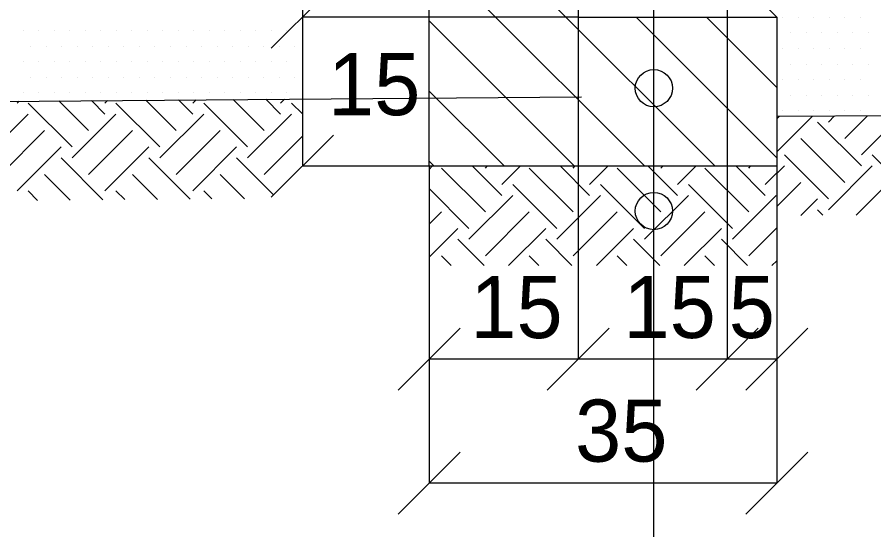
# Model space of a CAD drawing. Extents: x -219625893 to 7498339, y 5791790 to 5792761.
# Drawn here: x 7495350.16 to 7495367.41, y 5791855.88 to 5791866.2 of the extents above; entities that cross this region are included whole.
import ezdxf

# ---------------------------------------------------------------- set-up
doc = ezdxf.new("R2010")
doc.units = 0
for name, color, linetype in [('D_kons_wyp_grunt', 7, 'Continuous'), ('D_kons_wyp_pospolka', 7, 'Continuous'), ('D_robocze_1', 7, 'Continuous'), ('D_wymiary_500', 7, 'Continuous'), ('Level 10', 7, 'Continuous'), ('Level 8', 7, 'Continuous'), ('wymiary', 7, 'Continuous')]:
    doc.layers.add(name, color=color, linetype=linetype)

msp = doc.modelspace()

# ---------------------------------------------------------------- linework, layer by layer
at = {"layer": 'D_kons_wyp_grunt'}
for p, q in [((7495355.136, 5791863.919), (7495354.511, 5791864.543)), ((7495355.467, 5791864.25), (7495355.169, 5791864.549)), ((7495355.467, 5791864.471), (7495355.548, 5791864.552)), ((7495350.164, 5791864.471), (7495350.202, 5791864.509)), ((7495351.269, 5791863.587), (7495350.385, 5791864.471)), ((7495351.6, 5791863.919), (7495351.004, 5791864.515)), ((7495351.932, 5791864.25), (7495351.662, 5791864.521)), ((7495351.932, 5791864.471), (7495351.984, 5791864.523)), ((7495353.037, 5791863.587), (7495352.153, 5791864.471)), ((7495353.368, 5791863.919), (7495352.758, 5791864.529)), ((7495353.7, 5791864.25), (7495353.415, 5791864.535)), ((7495353.7, 5791864.471), (7495353.766, 5791864.538)), ((7495354.804, 5791863.587), (7495353.921, 5791864.471)), ((7495355.906, 5791864.254), (7495355.688, 5791864.471)), ((7495349.501, 5791863.367), (7495350.385, 5791864.25)), ((7495351.269, 5791863.367), (7495352.153, 5791864.25)), ((7495353.037, 5791863.367), (7495353.921, 5791864.25)), ((7495354.804, 5791863.367), (7495355.688, 5791864.25)), ((7495365.458, 5791863.492), (7495366.177, 5791864.21)), ((7495365.458, 5791864.155), (7495365.51, 5791864.207)), ((7495366.497, 5791864.089), (7495366.621, 5791864.213)), ((7495366.828, 5791863.757), (7495367.287, 5791864.216)), ((7495367.16, 5791863.426), (7495367.953, 5791864.219)), ((7495367.16, 5791863.205), (7495366.276, 5791864.089)), ((7495349.833, 5791863.035), (7495350.716, 5791863.919)), ((7495351.6, 5791863.035), (7495352.484, 5791863.919)), ((7495353.368, 5791863.035), (7495354.252, 5791863.919)), ((7495355.136, 5791863.035), (7495355.906, 5791863.805)), ((7495366.828, 5791862.873), (7495365.944, 5791863.757)), ((7495350.164, 5791862.704), (7495351.048, 5791863.587)), ((7495351.932, 5791862.704), (7495352.816, 5791863.587)), ((7495353.7, 5791862.704), (7495354.583, 5791863.587)), ((7495351.892, 5791862.522), (7495351.048, 5791863.367)), ((7495353.646, 5791862.536), (7495352.816, 5791863.367)), ((7495355.328, 5791862.622), (7495354.583, 5791863.367)), ((7495366.497, 5791862.542), (7495365.613, 5791863.426)), ((7495368.265, 5791862.542), (7495367.381, 5791863.426)), ((7495358.458, 5791863.135), (7495358.523, 5791863.199)), ((7495359.591, 5791862.279), (7495358.707, 5791863.163)), ((7495359.922, 5791862.61), (7495359.333, 5791863.199)), ((7495359.591, 5791863.163), (7495359.627, 5791863.199)), ((7495359.922, 5791862.831), (7495360.29, 5791863.199)), ((7495361.359, 5791862.279), (7495360.475, 5791863.163)), ((7495361.69, 5791862.61), (7495361.101, 5791863.199)), ((7495361.359, 5791863.163), (7495361.395, 5791863.199)), ((7495361.69, 5791862.831), (7495362.058, 5791863.199)), ((7495363.126, 5791862.279), (7495362.242, 5791863.163)), ((7495363.458, 5791862.61), (7495362.869, 5791863.199)), ((7495363.126, 5791863.163), (7495363.163, 5791863.199)), ((7495363.458, 5791862.831), (7495363.826, 5791863.199)), ((7495364.894, 5791862.279), (7495364.01, 5791863.163)), ((7495365.226, 5791862.61), (7495364.637, 5791863.199)), ((7495364.894, 5791863.163), (7495364.931, 5791863.199)), ((7495365.458, 5791863.05), (7495365.613, 5791863.205)), ((7495366.497, 5791862.321), (7495367.381, 5791863.205)), ((7495351.234, 5791862.517), (7495350.716, 5791863.035)), ((7495352.988, 5791862.531), (7495352.484, 5791863.035)), ((7495354.742, 5791862.545), (7495354.252, 5791863.035)), ((7495365.226, 5791862.831), (7495365.458, 5791863.064)), ((7495361.027, 5791861.948), (7495360.143, 5791862.831)), ((7495362.795, 5791861.948), (7495361.911, 5791862.831)), ((7495364.563, 5791861.948), (7495363.679, 5791862.831)), ((7495365.458, 5791862.387), (7495365.944, 5791862.873)), ((7495367.054, 5791862.215), (7495367.712, 5791862.873)), ((7495350.577, 5791862.512), (7495350.385, 5791862.704)), ((7495352.33, 5791862.526), (7495352.153, 5791862.704)), ((7495354.084, 5791862.54), (7495353.921, 5791862.704)), ((7495359.259, 5791861.948), (7495358.458, 5791862.749)), ((7495359.259, 5791861.727), (7495360.143, 5791862.61)), ((7495361.027, 5791861.727), (7495361.911, 5791862.61)), ((7495362.795, 5791861.727), (7495363.679, 5791862.61)), ((7495364.563, 5791861.727), (7495365.447, 5791862.61)), ((7495365.943, 5791862.209), (7495366.276, 5791862.542)), ((7495366.385, 5791862.211), (7495366.276, 5791862.321)), ((7495358.458, 5791862.03), (7495358.707, 5791862.279)), ((7495359.591, 5791861.395), (7495360.475, 5791862.279)), ((7495361.359, 5791861.395), (7495362.242, 5791862.279)), ((7495363.126, 5791861.395), (7495364.01, 5791862.279)), ((7495364.894, 5791861.395), (7495365.458, 5791861.959)), ((7495358.458, 5791861.367), (7495359.038, 5791861.948)), ((7495360.058, 5791861.199), (7495360.806, 5791861.948)), ((7495361.826, 5791861.199), (7495362.574, 5791861.948)), ((7495363.594, 5791861.199), (7495364.342, 5791861.948)), ((7495359.566, 5791861.199), (7495359.038, 5791861.727)), ((7495361.333, 5791861.199), (7495360.806, 5791861.727)), ((7495363.101, 5791861.199), (7495362.574, 5791861.727)), ((7495364.869, 5791861.199), (7495364.342, 5791861.727)), ((7495358.903, 5791861.199), (7495358.707, 5791861.395)), ((7495360.67, 5791861.199), (7495360.475, 5791861.395)), ((7495362.438, 5791861.199), (7495362.242, 5791861.395)), ((7495364.206, 5791861.199), (7495364.01, 5791861.395)), ((7495365.361, 5791861.199), (7495365.458, 5791861.296))]:
    msp.add_line(p, q, dxfattribs=at)
at = {"layer": 'D_kons_wyp_pospolka'}
for p, q in [((7495365.58, 5791866.195), (7495365.58, 5791866.195)), ((7495365.892, 5791866.195), (7495365.892, 5791866.195)), ((7495366.205, 5791866.195), (7495366.205, 5791866.195)), ((7495366.517, 5791866.195), (7495366.517, 5791866.195)), ((7495366.83, 5791866.195), (7495366.83, 5791866.195)), ((7495367.142, 5791866.195), (7495367.142, 5791866.195)), ((7495350.283, 5791865.932), (7495350.283, 5791865.932)), ((7495350.596, 5791865.932), (7495350.596, 5791865.932)), ((7495350.908, 5791865.932), (7495350.908, 5791865.932)), ((7495351.221, 5791865.932), (7495351.221, 5791865.932)), ((7495351.533, 5791865.932), (7495351.533, 5791865.932)), ((7495351.846, 5791865.932), (7495351.846, 5791865.932)), ((7495352.158, 5791865.932), (7495352.158, 5791865.932)), ((7495352.471, 5791865.932), (7495352.471, 5791865.932)), ((7495352.783, 5791865.932), (7495352.783, 5791865.932)), ((7495353.096, 5791865.932), (7495353.096, 5791865.932)), ((7495353.408, 5791865.932), (7495353.408, 5791865.932)), ((7495353.721, 5791865.932), (7495353.721, 5791865.932)), ((7495354.033, 5791865.932), (7495354.033, 5791865.932)), ((7495354.346, 5791865.932), (7495354.346, 5791865.932)), ((7495354.658, 5791865.932), (7495354.658, 5791865.932)), ((7495354.971, 5791865.932), (7495354.971, 5791865.932)), ((7495355.283, 5791865.932), (7495355.283, 5791865.932)), ((7495355.596, 5791865.932), (7495355.596, 5791865.932)), ((7495365.736, 5791865.883), (7495365.736, 5791865.883)), ((7495366.048, 5791865.883), (7495366.048, 5791865.883)), ((7495366.361, 5791865.883), (7495366.361, 5791865.883)), ((7495366.673, 5791865.883), (7495366.673, 5791865.883)), ((7495366.986, 5791865.883), (7495366.986, 5791865.883)), ((7495367.298, 5791865.883), (7495367.298, 5791865.883)), ((7495350.439, 5791865.619), (7495350.439, 5791865.619)), ((7495350.752, 5791865.619), (7495350.752, 5791865.619)), ((7495351.064, 5791865.619), (7495351.064, 5791865.619)), ((7495351.377, 5791865.619), (7495351.377, 5791865.619)), ((7495351.689, 5791865.619), (7495351.689, 5791865.619)), ((7495352.002, 5791865.619), (7495352.002, 5791865.619)), ((7495352.314, 5791865.619), (7495352.314, 5791865.619)), ((7495352.627, 5791865.619), (7495352.627, 5791865.619)), ((7495352.939, 5791865.619), (7495352.939, 5791865.619)), ((7495353.252, 5791865.619), (7495353.252, 5791865.619)), ((7495353.564, 5791865.619), (7495353.564, 5791865.619)), ((7495353.877, 5791865.619), (7495353.877, 5791865.619)), ((7495354.189, 5791865.619), (7495354.189, 5791865.619)), ((7495354.502, 5791865.619), (7495354.502, 5791865.619)), ((7495354.814, 5791865.619), (7495354.814, 5791865.619)), ((7495355.127, 5791865.619), (7495355.127, 5791865.619)), ((7495355.439, 5791865.619), (7495355.439, 5791865.619)), ((7495355.752, 5791865.619), (7495355.752, 5791865.619)), ((7495365.58, 5791865.57), (7495365.58, 5791865.57)), ((7495365.892, 5791865.57), (7495365.892, 5791865.57)), ((7495366.205, 5791865.57), (7495366.205, 5791865.57)), ((7495366.517, 5791865.57), (7495366.517, 5791865.57)), ((7495366.83, 5791865.57), (7495366.83, 5791865.57)), ((7495367.142, 5791865.57), (7495367.142, 5791865.57)), ((7495350.283, 5791865.307), (7495350.283, 5791865.307)), ((7495350.596, 5791865.307), (7495350.596, 5791865.307)), ((7495350.908, 5791865.307), (7495350.908, 5791865.307)), ((7495351.221, 5791865.307), (7495351.221, 5791865.307)), ((7495351.533, 5791865.307), (7495351.533, 5791865.307)), ((7495351.846, 5791865.307), (7495351.846, 5791865.307)), ((7495352.158, 5791865.307), (7495352.158, 5791865.307)), ((7495352.471, 5791865.307), (7495352.471, 5791865.307)), ((7495352.783, 5791865.307), (7495352.783, 5791865.307)), ((7495353.096, 5791865.307), (7495353.096, 5791865.307)), ((7495353.408, 5791865.307), (7495353.408, 5791865.307)), ((7495353.721, 5791865.307), (7495353.721, 5791865.307)), ((7495354.033, 5791865.307), (7495354.033, 5791865.307)), ((7495354.346, 5791865.307), (7495354.346, 5791865.307)), ((7495354.658, 5791865.307), (7495354.658, 5791865.307)), ((7495354.971, 5791865.307), (7495354.971, 5791865.307)), ((7495355.283, 5791865.307), (7495355.283, 5791865.307)), ((7495355.596, 5791865.307), (7495355.596, 5791865.307)), ((7495365.736, 5791865.258), (7495365.736, 5791865.258)), ((7495366.048, 5791865.258), (7495366.048, 5791865.258)), ((7495366.361, 5791865.258), (7495366.361, 5791865.258)), ((7495366.673, 5791865.258), (7495366.673, 5791865.258)), ((7495366.986, 5791865.258), (7495366.986, 5791865.258)), ((7495367.298, 5791865.258), (7495367.298, 5791865.258)), ((7495350.439, 5791864.994), (7495350.439, 5791864.994)), ((7495350.752, 5791864.994), (7495350.752, 5791864.994)), ((7495351.064, 5791864.994), (7495351.064, 5791864.994)), ((7495351.377, 5791864.994), (7495351.377, 5791864.994)), ((7495351.689, 5791864.994), (7495351.689, 5791864.994)), ((7495352.002, 5791864.994), (7495352.002, 5791864.994)), ((7495352.314, 5791864.994), (7495352.314, 5791864.994)), ((7495352.627, 5791864.994), (7495352.627, 5791864.994)), ((7495352.939, 5791864.994), (7495352.939, 5791864.994)), ((7495353.252, 5791864.994), (7495353.252, 5791864.994)), ((7495353.564, 5791864.994), (7495353.564, 5791864.994)), ((7495353.877, 5791864.994), (7495353.877, 5791864.994)), ((7495354.189, 5791864.994), (7495354.189, 5791864.994)), ((7495354.502, 5791864.994), (7495354.502, 5791864.994)), ((7495354.814, 5791864.994), (7495354.814, 5791864.994)), ((7495355.127, 5791864.994), (7495355.127, 5791864.994)), ((7495355.439, 5791864.994), (7495355.439, 5791864.994)), ((7495355.752, 5791864.994), (7495355.752, 5791864.994)), ((7495365.58, 5791864.945), (7495365.58, 5791864.945)), ((7495365.892, 5791864.945), (7495365.892, 5791864.945)), ((7495366.205, 5791864.945), (7495366.205, 5791864.945)), ((7495366.517, 5791864.945), (7495366.517, 5791864.945)), ((7495366.83, 5791864.945), (7495366.83, 5791864.945)), ((7495367.142, 5791864.945), (7495367.142, 5791864.945)), ((7495350.283, 5791864.682), (7495350.283, 5791864.682)), ((7495350.596, 5791864.682), (7495350.596, 5791864.682)), ((7495350.908, 5791864.682), (7495350.908, 5791864.682)), ((7495351.221, 5791864.682), (7495351.221, 5791864.682)), ((7495351.533, 5791864.682), (7495351.533, 5791864.682)), ((7495351.846, 5791864.682), (7495351.846, 5791864.682)), ((7495352.158, 5791864.682), (7495352.158, 5791864.682)), ((7495352.471, 5791864.682), (7495352.471, 5791864.682)), ((7495352.783, 5791864.682), (7495352.783, 5791864.682)), ((7495353.096, 5791864.682), (7495353.096, 5791864.682)), ((7495353.408, 5791864.682), (7495353.408, 5791864.682)), ((7495353.721, 5791864.682), (7495353.721, 5791864.682)), ((7495354.033, 5791864.682), (7495354.033, 5791864.682)), ((7495354.346, 5791864.682), (7495354.346, 5791864.682)), ((7495354.658, 5791864.682), (7495354.658, 5791864.682)), ((7495354.971, 5791864.682), (7495354.971, 5791864.682)), ((7495355.283, 5791864.682), (7495355.283, 5791864.682)), ((7495355.596, 5791864.682), (7495355.596, 5791864.682)), ((7495365.736, 5791864.633), (7495365.736, 5791864.633)), ((7495366.048, 5791864.633), (7495366.048, 5791864.633)), ((7495366.361, 5791864.633), (7495366.361, 5791864.633)), ((7495366.673, 5791864.633), (7495366.673, 5791864.633)), ((7495366.986, 5791864.633), (7495366.986, 5791864.633)), ((7495367.298, 5791864.633), (7495367.298, 5791864.633)), ((7495365.58, 5791864.32), (7495365.58, 5791864.32)), ((7495365.892, 5791864.32), (7495365.892, 5791864.32)), ((7495366.205, 5791864.32), (7495366.205, 5791864.32)), ((7495366.517, 5791864.32), (7495366.517, 5791864.32)), ((7495366.83, 5791864.32), (7495366.83, 5791864.32)), ((7495367.142, 5791864.32), (7495367.142, 5791864.32))]:
    msp.add_line(p, q, dxfattribs=at)
at = {"layer": 'D_robocze_1'}
for p, q in [((7495364.216, 5791863.199), (7495358.458, 5791868.957)), ((7495362.801, 5791863.199), (7495358.458, 5791867.543)), ((7495361.387, 5791863.199), (7495358.458, 5791866.128)), ((7495365.458, 5791863.371), (7495362.63, 5791866.199)), ((7495365.458, 5791864.785), (7495364.044, 5791866.199)), ((7495359.973, 5791863.199), (7495358.458, 5791864.714)), ((7495358.559, 5791863.199), (7495358.458, 5791863.3))]:
    msp.add_line(p, q, dxfattribs=at)
at = {"layer": 'D_wymiary_500'}
for p, q in [((7495355.906, 5791869.199), (7495355.906, 5791863.199)), ((7495364.458, 5791867.199), (7495364.458, 5791859.316)), ((7495361.458, 5791866.199), (7495355.906, 5791866.199)), ((7495361.458, 5791866.199), (7495361.458, 5791859.316)), ((7495365.458, 5791864.207), (7495414.458, 5791864.452)), ((7495358.458, 5791863.199), (7495355.906, 5791863.199)), ((7495358.458, 5791863.199), (7495358.458, 5791856.816)), ((7495365.458, 5791863.199), (7495365.458, 5791856.816)), ((7495365.458, 5791859.316), (7495358.458, 5791859.316)), ((7495365.458, 5791856.816), (7495358.458, 5791856.816))]:
    msp.add_line(p, q, dxfattribs=at)
at = {"layer": 'Level 10'}
for p, q in [((7495359.094, 5791863.199), (7495359.094, 5791863.199)), ((7495363.337, 5791863.199), (7495363.337, 5791863.199))]:
    msp.add_line(p, q, dxfattribs=at)
at = {"layer": 'Level 8'}
for p, q in [((7495358.458, 5791863.199), (7495358.458, 5791869.199)), ((7495364.458, 5791867.199), (7495365.458, 5791866.199)), ((7495365.458, 5791866.199), (7495365.458, 5791863.199)), ((7495365.458, 5791863.199), (7495358.458, 5791863.199))]:
    msp.add_line(p, q, dxfattribs=at)
msp.add_lwpolyline([(7495361.458, 5791867.199), (7495361.458, 5791866.199), (7495365.458, 5791866.199)], dxfattribs=at)
at = {"layer": 'wymiary'}
for p, q in [((7495362.983, 5791843.439), (7495362.983, 5791869.945)), ((7495355.28, 5791865.575), (7495356.531, 5791866.824)), ((7495298.471, 5791864.094), (7495361.527, 5791864.6)), ((7495355.28, 5791862.575), (7495356.531, 5791863.824)), ((7495357.833, 5791858.691), (7495359.084, 5791859.94)), ((7495360.833, 5791858.691), (7495362.084, 5791859.94)), ((7495363.833, 5791858.691), (7495365.084, 5791859.94)), ((7495364.833, 5791858.691), (7495366.084, 5791859.94)), ((7495357.833, 5791856.191), (7495359.084, 5791857.44)), ((7495364.833, 5791856.191), (7495366.084, 5791857.44))]:
    msp.add_line(p, q, dxfattribs=at)
for centre in [(7495362.983, 5791864.771), (7495362.983, 5791862.296)]:
    msp.add_circle(centre, 0.375, dxfattribs=at)

# ---------------------------------------------------------------- texts
at = {"layer": 'D_wymiary_500'}
for s, p in [('15', (7495356.423, 5791864.226)), ('15', (7495359.288, 5791859.737)), ('15', (7495362.371, 5791859.739)), ('5', (7495364.492, 5791859.739)), ('35', (7495361.397, 5791857.249))]:
    msp.add_text(s, height=1.25, rotation=0.0429, dxfattribs=at).set_placement(p)

doc.saveas('drawing.dxf')
